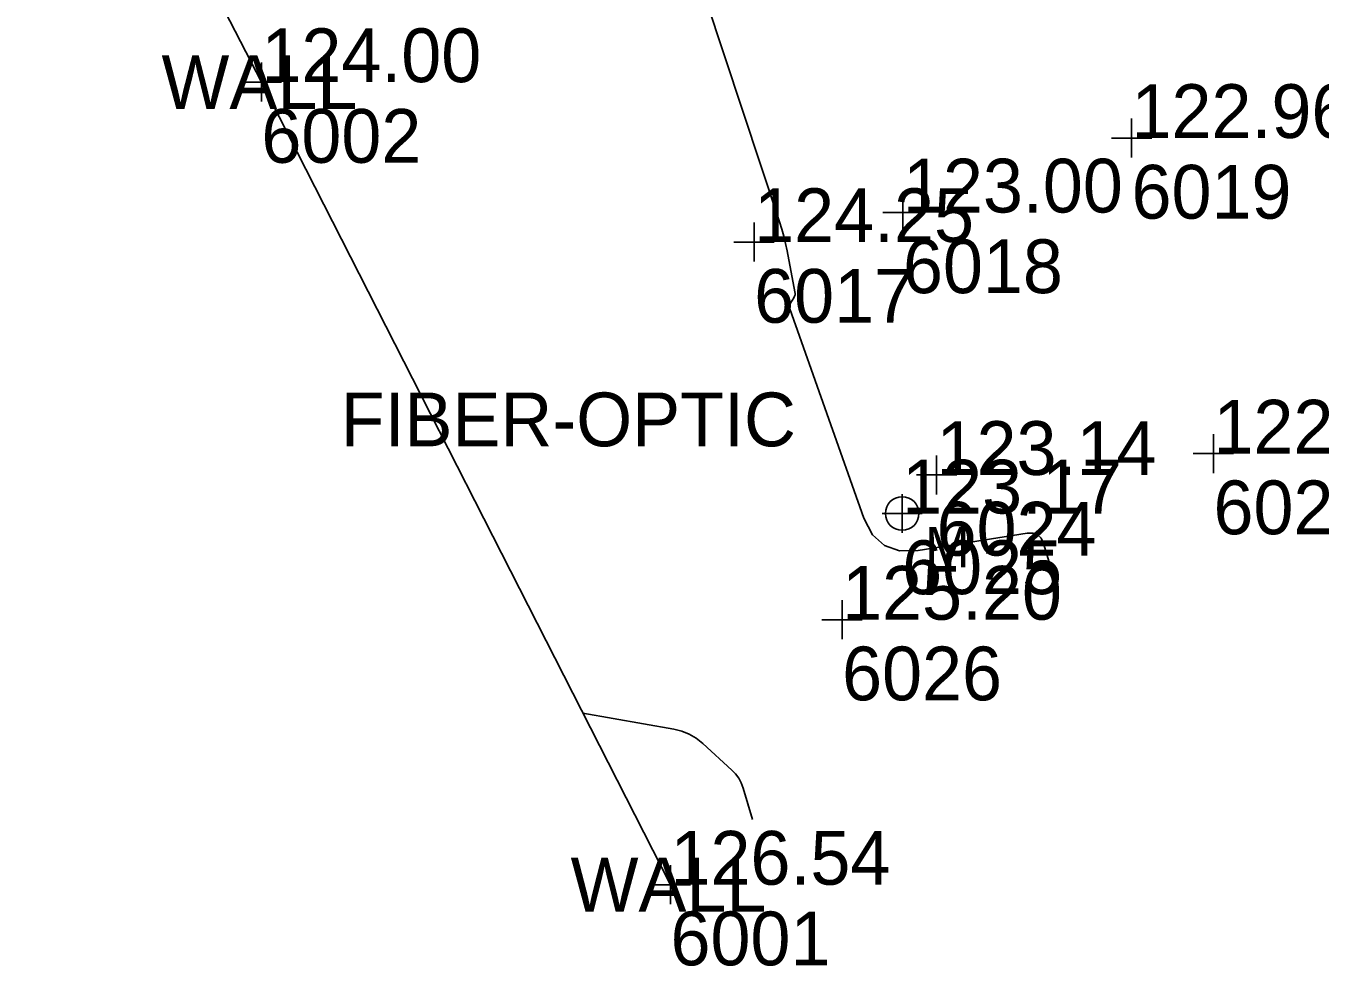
# Model space of a CAD drawing. Extents: x 13482745 to 13483091, y 311698 to 312158.
# Drawn here: x 13482900.4 to 13482977.4, y 311807.2 to 311863.1 of the extents above; entities that cross this region are included whole.
import ezdxf

# ---------------------------------------------------------------- set-up
doc = ezdxf.new("R2010")
doc.units = 0
for name, color, linetype in [('V-BLDG-OTLN', 7, 'Continuous'), ('V-SITE-FEAT', 7, 'Continuous'), ('V-SITE-IDEN', 7, 'Continuous'), ('V-SITE-SPOT', 7, 'Continuous'), ('V-SURV-PNTS', 7, 'Continuous'), ('V-TOPO-LINE-IDEN', 7, 'Continuous'), ('V-TOPO-MINR', 7, 'Continuous'), ('V-TOPO-SPOT', 7, 'Continuous')]:
    doc.layers.add(name, color=color, linetype=linetype)

msp = doc.modelspace()

# ---------------------------------------------------------------- linework, layer by layer
at = {"layer": 'V-BLDG-OTLN'}
msp.add_lwpolyline([(13482938.745, 311812.013), (13482914.39, 311859.782), (13482907.168, 311873.788), (13482923.791, 311882.044), (13482902.533, 311922.545), (13482900.37, 311926.805)], dxfattribs=at)
at = {"layer": 'V-SITE-FEAT'}
msp.add_circle((13482952.536, 311834.107), 1, dxfattribs=at)
at = {"layer": 'V-SITE-SPOT'}
for p, q in [((13482914.39, 311860.942), (13482914.39, 311858.622)), ((13482913.19, 311859.782), (13482915.59, 311859.782)), ((13482952.536, 311835.267), (13482952.536, 311832.947)), ((13482951.336, 311834.107), (13482953.736, 311834.107)), ((13482938.745, 311813.173), (13482938.745, 311810.853)), ((13482937.545, 311812.013), (13482939.945, 311812.013))]:
    msp.add_line(p, q, dxfattribs=at)
at = {"layer": 'V-TOPO-MINR'}
for points in [[(13482961.599, 311830.154), (13482960.944, 311832.324), (13482960.802, 311832.633), (13482960.594, 311832.837), (13482960.32, 311832.936), (13482959.98, 311832.929), (13482953.489, 311831.907), (13482952.382, 311831.884), (13482951.476, 311832.197), (13482950.769, 311832.845), (13482950.262, 311833.829), (13482945.855, 311846.293), (13482945.834, 311846.381), (13482945.833, 311846.466), (13482945.852, 311846.55), (13482945.892, 311846.631), (13482946.091, 311846.952), (13482946.133, 311847.034), (13482946.157, 311847.119), (13482946.165, 311847.207), (13482946.155, 311847.298), (13482945.682, 311849.741), (13482945.59, 311850.177), (13482945.484, 311850.61), (13482945.365, 311851.039), (13482945.231, 311851.464), (13482940.842, 311864.729)], [(13482933.535, 311822.231), (13482938.942, 311821.273), (13482939.419, 311821.154), (13482939.866, 311820.973), (13482940.281, 311820.729), (13482940.665, 311820.422), (13482942.396, 311818.835), (13482942.618, 311818.603), (13482942.804, 311818.348), (13482942.953, 311818.07), (13482943.066, 311817.768), (13482943.632, 311815.892)]]:
    msp.add_lwpolyline(points, dxfattribs=at)
at = {"layer": 'V-TOPO-SPOT'}
for p, q in [((13482966.191, 311857.617), (13482966.191, 311855.297)), ((13482964.991, 311856.457), (13482967.391, 311856.457)), ((13482952.585, 311853.183), (13482952.585, 311850.863)), ((13482951.385, 311852.023), (13482953.785, 311852.023)), ((13482943.724, 311851.422), (13482943.724, 311849.102)), ((13482942.524, 311850.262), (13482944.924, 311850.262)), ((13482971.069, 311838.832), (13482971.069, 311836.512)), ((13482954.585, 311837.561), (13482954.585, 311835.241)), ((13482969.869, 311837.672), (13482972.269, 311837.672)), ((13482953.385, 311836.401), (13482955.785, 311836.401)), ((13482948.96, 311828.946), (13482948.96, 311826.626)), ((13482947.76, 311827.786), (13482950.16, 311827.786))]:
    msp.add_line(p, q, dxfattribs=at)

# ---------------------------------------------------------------- texts
at = {"layer": 'V-SITE-FEAT'}
msp.add_text('M', height=2.4, rotation=360, dxfattribs=at).set_placement((13482953.896, 311830.907))
at = {"layer": 'V-SITE-IDEN'}
msp.add_text('FIBER-OPTIC', height=3.2, dxfattribs=at).set_placement((13482919.108, 311838.107))
at = {"layer": 'V-SITE-SPOT'}
for s, p in [('124.00', (13482914.39, 311859.782)), ('123.17', (13482952.536, 311834.107)), ('126.54', (13482938.745, 311812.013))]:
    msp.add_text(s, height=3.2, dxfattribs=at).set_placement(p)
at = {"layer": 'V-SURV-PNTS'}
for s, p in [('6002', (13482914.39, 311854.982)), ('6019', (13482966.191, 311851.657)), ('6018', (13482952.585, 311847.223)), ('6017', (13482943.724, 311845.462)), ('6023', (13482971.069, 311832.872)), ('6024', (13482954.585, 311831.601)), ('6025', (13482952.536, 311829.307)), ('6026', (13482948.96, 311822.986)), ('6001', (13482938.745, 311807.213))]:
    msp.add_text(s, height=3.2, dxfattribs=at).set_placement(p)
at = {"layer": 'V-TOPO-LINE-IDEN'}
for p in [(13482908.443, 311858.182), (13482932.799, 311810.413)]:
    msp.add_text('WALL', height=3.2, dxfattribs=at).set_placement(p)
at = {"layer": 'V-TOPO-SPOT'}
for s, p in [('122.96', (13482966.191, 311856.457)), ('123.00', (13482952.585, 311852.023)), ('124.25', (13482943.724, 311850.262)), ('122.95', (13482971.069, 311837.672)), ('123.14', (13482954.585, 311836.401)), ('125.20', (13482948.96, 311827.786))]:
    msp.add_text(s, height=3.2, dxfattribs=at).set_placement(p)

doc.saveas('drawing.dxf')
